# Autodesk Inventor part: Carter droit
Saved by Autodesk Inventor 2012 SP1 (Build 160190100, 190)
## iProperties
Created: 2014-12
Part Number: Carter droit
Material: Default
Document SubType Name: Modeling
Designer: Bruno
Density: 1 g/cm^3
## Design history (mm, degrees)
node "Carter droit1"
node "Carter droit"
node "Carter droit_1"
node "Carter droit_2"
node "Carter droit_3"
node "Carter droit_4"
node "Carter droit_5"
node "Carter droit_6"
node "Base1"
node "Base2"
node "Base3"
node "Base4"
node "Base5"
node "Base6"
node "Base7"
feature "Composite1"
body "Srf1"
